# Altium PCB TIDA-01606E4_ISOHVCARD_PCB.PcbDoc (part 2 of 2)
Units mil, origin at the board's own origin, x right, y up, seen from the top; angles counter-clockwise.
Board outline 2900 x 1300 mil, 4 copper layers (Top Layer, Signal Layer 1, Signal Layer 2, Bottom Layer), stack 61.6 mil thick; 82 components, 40 nets, 166 pads, 21 vias.
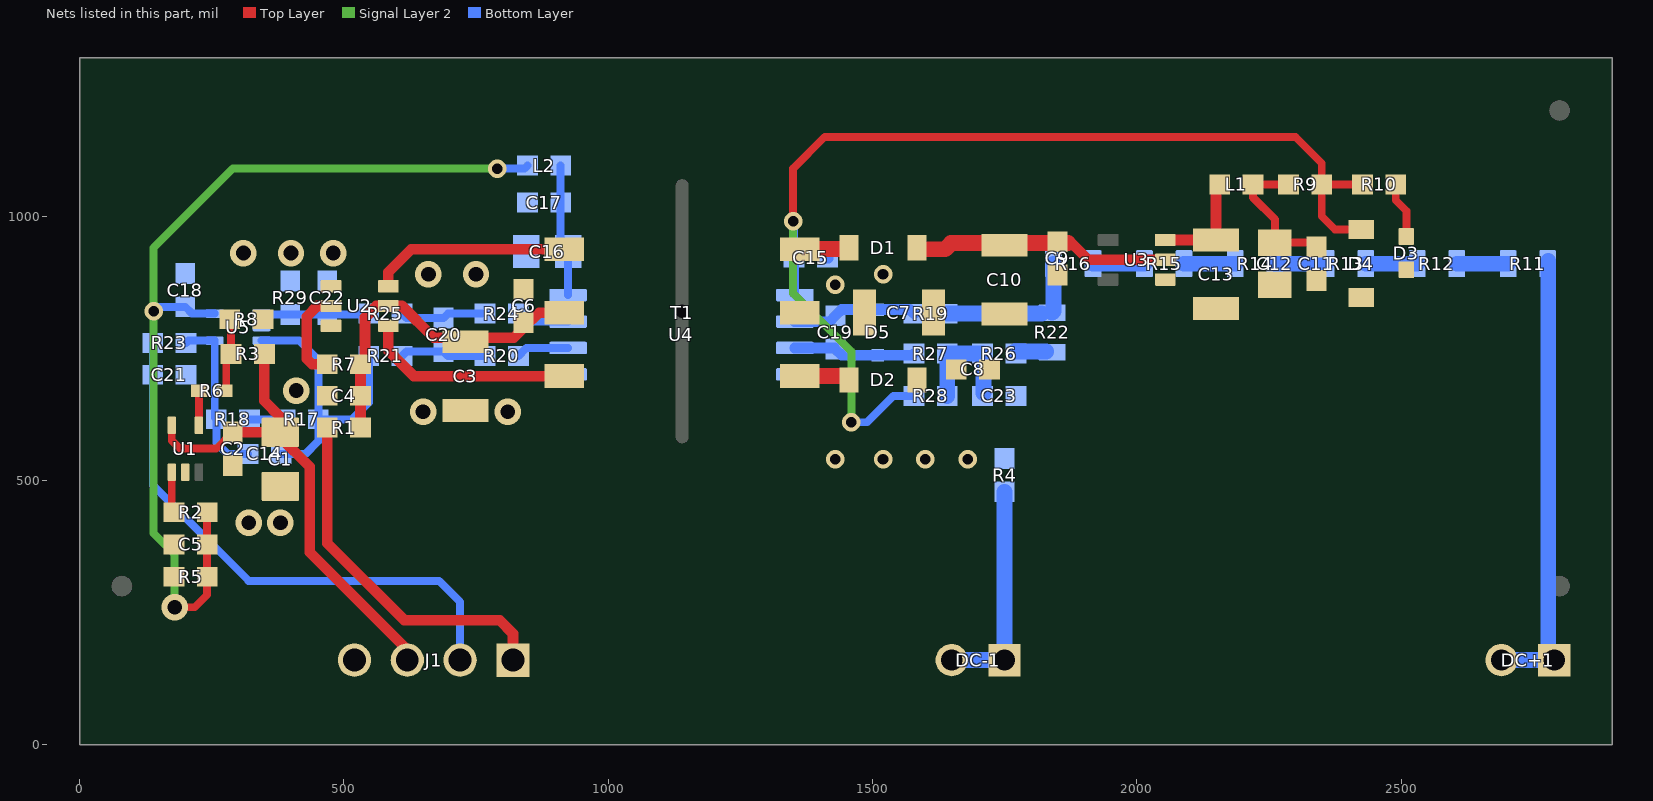
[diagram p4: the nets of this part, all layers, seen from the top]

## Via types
v1: diameter 50, hole 28, Top Layer to Bottom Layer, tented both sides, 11 vias
v2: diameter 35, hole 20, Top Layer to Bottom Layer, tented both sides, 10 vias

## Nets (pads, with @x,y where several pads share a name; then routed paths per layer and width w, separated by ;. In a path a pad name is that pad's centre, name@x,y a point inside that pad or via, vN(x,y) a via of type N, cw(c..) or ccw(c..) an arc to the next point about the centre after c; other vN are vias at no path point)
3.3V: C1.1 C2.2 J1.3 R3.2 U1.5 | length 945.2
  Top Layer w15: U1.5@174.41,604.29 174.41,575.59 190,560 258.5,560 C2.2@290,591.5
  Top Layer w20: C2.2@290,591.5 290.31,591.18 C1.1@380,591.18 ; R3.2@349.61,739.26 349.61,650.39 380,620 C1.1@380,591.18 ; J1.3@620,160 620,180 435.55,364.45 435.55,525.55 380,581.1 C1.1@380,591.18
3.3V_ISO: C15.2 D4.1 R9.2 R10.1 R28.1 U4.1 | length 2108.8
  Top Layer w15: v2(1350,990) 1350,1090 1410,1150 2300,1150 2350,1100 R9.2@2350,1060 ; D4.1@2420,974.47 2375.53,974.47 2350,1000 R9.2@2350,1060 ; R10.1@2427.01,1060 R9.2@2350,1060
  Signal Layer 2 w15: v2(1350,990) 1350,853.82 1460,743.82 v2(1460,610)
  Bottom Layer w15: v2(1350,990) 1351.76,988.24 C15.2@1351.76,921.55 1353.27,920.04 U4.1@1353.27,850.55 ; v2(1460,610) 1489.93,610 1539.93,660 ; 1539.97,659.97 R28.1@1578.52,659.97
3.3V_LS: C5.2 C18.1 L2.2 R2.1 R5.1 U5.5 | length 1830.4
  Top Layer w15: v1(180,260) 217.84,260 241.5,283.65 R5.1@241.5,317.71 R2.1@241.5,450
  Signal Layer 2 w15: v1(180,260) 180,360 140,400 v2(140,820) 140,940 290,1090 v2(790,1090)
  Bottom Layer w15: v2(140,820) 148.5,828.5 C18.1@200,828.5 212.91,815.59 U5.5@255.71,815.59 ; v2(790,1090) 841.65,1090 L2.2@847.2,1095.55
5V: J1.1 R1.2 | length 691
  Top Layer w20: R1.2@468.5,600 468.5,381.5 614.63,235.37 794.63,235.37 820,210 J1.1@820,160
6V: C7.1 C8.1 C9.1 C10.2 D1.1 D2.1 U3.2 | length 487.5
  Top Layer w20: 1870,948.94 1877.01,948.94 1908.5,917.45 U3.2@2054.13,917.45
  Top Layer w30: D1.1@1584.47,937.45 1637.45,937.45 1648.94,948.94 1870,948.94
DC+: DC+1.1 DC+1.2 R11.2 | length 860.2
  Bottom Layer w30: DC+1.2@2690,160 DC+1.1@2790,160 2778.7,171.3 R11.2@2778.7,915.55
DC-: DC-1.1 DC-1.2 R4.1 | length 418.5
  Bottom Layer w30: DC-1.2@1650,160 DC-1.1@1750,160 1749.93,160.07 R4.1@1750,478.5
GND: C1.2 C2.1 C3.1 C4.1 C5.1 C6.1 C16.1 C17.1 C18.2 C21.2 C22.2 J1.4 R5.2 R8.1 R29.1 U1.2 U2.4 U2.6 U4.5 U5.2
  other v1: 320,420 380,420 650,630 810,630 410,670 660,890 750,890 310,930 400,930 480,930
GND_AMC: C7.2 C8.2 C9.2 C10.1 C11.2 C12.1 C13.1 C15.1 C23.1 D3.1 D4.2 R4.2 R22.1 R26.1 T1.5 U3.1 U4.4 | length 60.9
  Bottom Layer w20: C15.1@1414.75,921.55 C15.1@1416.3,920
  Bottom Layer w30: R26.1@1770.02,744.02 R22.1@1828.72,744.02
  other v2: 1430,540 1520,540 1600,540 1680,540 1430,870 1520,890
NetC3_2: C3.2 C4.2 C6.2 R1.1 R7.1 T1.2 U2.2 | length 642.7
  Top Layer w20: R1.1@531.5,600 R7.1@531.5,720 540,728.5 540,808.35 561.65,830 610,830 670,770 821.5,770 840,788.5 840.67,788.5 869.62,817.45 T1.2@917.36,817.45
NetC11_1: C11.1 C12.2 L1.2 R9.1 | length 276.3
  Top Layer w15: R9.1@2287.01,1060 L1.2@2220,1060 2220,1035.3 2261.4,993.9 C12.2@2261.4,950 2331.5,950 C11.1@2340,941.5
NetC13_2: C13.2 L1.1 U3.3 | length 203.9
  Top Layer w20: U3.3@2054.13,954.85 2149.89,954.85 C13.2@2150,954.96 2150,1052.99 L1.1@2157.01,1060
NetC14_1: C14.1 R17.1 R21.2 U5.3 | length 553.5
  Bottom Layer w15: U5.3@344.29,764.41 415.59,764.41 451.69,728.31 R17.1@451.69,615.55 ; C14.1@381.5,550 427.27,550 451.69,574.43 R17.1@451.69,615.55 ; R21.2@547.2,735.55 547.2,647.2 515.55,615.55 R17.1@451.69,615.55
NetC14_2: C14.2 R18.1 R23.1 U5.4 | length 319
  Bottom Layer w15: R23.1@201.5,760 205.91,764.41 U5.4@255.71,764.41 255.71,618.54 R18.1@258.7,615.55 258.7,571.3 280,550 C14.2@318.5,550
NetC16_2: C16.2 C17.2 L2.1 U4.8 | length 251.2
  Bottom Layer w15: L2.1@910.2,1095.55 C17.2@910.2,1025.55 910.2,947.5 C16.2@924.7,933 924.13,932.43 U4.8@924.13,850.55
NetC19_1: C19.1 D5.2 R19.2 U4.2 | length 238.1
  Bottom Layer w20: U4.2@1353.27,800.55 1419.06,800.55 C19.1@1430,811.5 1441.81,823.31 D5.2@1510,823.31 1570.93,823.31 R19.2@1578.72,815.52
NetC19_2: C19.2 D5.1 R27.2 U4.3 | length 232.4
  Bottom Layer w20: U4.3@1353.27,750.55 1427.95,750.55 C19.2@1430,748.5 1441.81,736.69 D5.1@1510,736.69 1575.25,736.69 R27.2@1578.52,739.97
NetC20_1: C20.1 R20.2 R21.1 | length 164.1
  Bottom Layer w15: R21.1@610.2,735.55 618.7,744.06 C20.1@688.7,744.06 697.2,735.55 R20.2@767.2,735.55
NetC20_2: C20.2 R24.2 R25.1 | length 164.1
  Bottom Layer w15: R25.1@610.2,815.55 618.7,807.05 C20.2@688.7,807.05 697.2,815.55 R24.2@767.2,815.55
NetC22_1: C22.1 R25.2 R29.2 U5.1 | length 201.9
  Bottom Layer w15: U5.1@345.94,814.06 R29.2@398.7,814.06 C22.1@468.7,814.06 545.71,814.06 R25.2@547.2,815.55
NetC23_2: C23.2 R26.2 R27.1 R28.2 | length 217
  Bottom Layer w30: R28.2@1641.51,659.97 R27.1@1641.51,739.97 R26.2@1708.52,739.97 ; C23.2@1710.02,665.52 R26.2@1710.02,735.52
NetD1_2: D1.2 T1.6 | length 92.8
  Top Layer w30: T1.6@1362.64,937.53 D1.2@1455.45,937.53
NetD2_2: D2.2 T1.4 | length 92.8
  Top Layer w30: T1.4@1362.64,697.37 D2.2@1455.45,697.37
NetD3_2: D3.2 R10.2 | length 106.8
  Top Layer w15: R10.2@2490,1060 2490,1030 2510,1010 D3.2@2510,961.5
NetR2_2: R2.2 U1.1 | length 67.4
  Top Layer w15: U1.1@174.41,515.71 174.41,454.09 R2.2@178.5,450
NetR3_1: R3.1 R6.2 R8.2 | length 139.8
  Top Layer w15: R6.2@277.56,670 277.56,730.2 R3.1@286.62,739.26 286.62,802.69 R8.2@284.23,805.09
NetR6_1: R6.1 U1.4 | length 67
  Top Layer w15: R6.1@222.44,670 225.59,666.85 U1.4@225.59,604.29
NetR7_2: R7.2 U2.5 | length 176.8
  Top Layer w20: R7.2@468.5,720 440,720 430,730 430,810 450,830 U2.5@475.87,830
NetR11_1: R11.1 R12.2 | length 97.2
  Bottom Layer w30: R12.2@2605.4,910 R11.1@2702.6,910
NetR12_1: R12.1 R13.2 | length 97.2
  Bottom Layer w30: R13.2@2433.4,910 R12.1@2530.6,910
NetR13_1: R13.1 R14.2 | length 97.2
  Bottom Layer w30: R14.2@2261.4,910 R13.1@2358.6,910
NetR14_1: R14.1 R15.2 | length 97.2
  Bottom Layer w30: R15.2@2089.4,910 R14.1@2186.6,910
NetR15_1: R15.1 R16.2 | length 97.2
  Bottom Layer w30: R16.2@1917.4,910 R15.1@2014.6,910
NetR16_1: R16.1 R19.1 R22.2 | length 272.2
  Bottom Layer w30: R19.1@1641.71,815.52 R22.2@1820.21,815.52 ; R22.2@1840,817.4 1842.6,820 R16.1@1842.6,910
NetR17_2: R17.2 R18.2 | length 67
  Bottom Layer w15: R18.2@321.69,615.55 R17.2@388.7,615.55
NetR20_1: R20.1 U4.6 | length 100.2
  Bottom Layer w15: R20.1@830.2,735.55 845.2,750.55 U4.6@924.13,750.55
NetR24_1: R24.1 U4.7 | length 100.2
  Bottom Layer w15: R24.1@830.2,815.55 845.2,800.55 U4.7@924.13,800.55
NetT1_1: T1.1 U2.3 | length 377.9
  Top Layer w20: U2.3@584.13,867.4 584.13,894.13 627.53,937.53 T1.1@917.36,937.53
NetT1_3: T1.3 U2.1 | length 400
  Top Layer w20: U2.1@584.13,792.6 584.13,745.87 632.63,697.37 T1.3@917.36,697.37
Vdc_SEN: C21.1 J1.2 R23.2 | length 1051.7
  Bottom Layer w15: R23.2@138.5,760 138.5,491.5 320,310 680,310 720,270 J1.2@720,160
pads on no net: FID1.1 FID2.1 FID3.1 LBL1.0 U1.3 U3.4 U3.5

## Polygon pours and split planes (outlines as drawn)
6V on Top Layer "TOP_LAYER_6V_P000" (solid, remove dead copper, pour order 0): 1560,990 1680,990 1680,630 1560,630
GND_AMC on Top Layer "TOP_LAYER_GND_AMC_P010" (solid, remove dead copper, pour order 10): 1360,1200 2640,1200 2640,520 1360,520
GND on Top Layer "TOP_LAYER_GND_P002" (solid, remove dead copper, pour order 2): 0,1200 900,1200 900,100 0,100
GND_AMC on Bottom Layer "BOTTOM_LAYER_GND_AMC_P012" (solid, remove dead copper, pour order 12): 1360,960 1770,960 1860.5,869.5 1860.5,520 1360,520
GND on Bottom Layer "BOTTOM_LAYER_GND_P006" (solid, remove dead copper, pour order 6): 0,1200 900,1200 900,100 0,100
GND on Bottom Layer "BOTTOM_LAYER_GND_P004" (solid, remove dead copper, pour order 4): 0,1200 900,1200 900,100 0,100
GND on Signal Layer 1 "SIGNAL_LAYER_1_GND_P008" (solid, remove dead copper, pour order 8): 0,1200 900,1200 900,100 0,100
no net on Top Solder "NONET_L-01_P-001" (solid): 982.52,1160 1297.48,1160 1297.48,480 982.52,480
no net on Bottom Solder "NONET_L-01_P-001" (solid): 982.52,1087.37 1297.48,1087.37 1297.48,407.37 982.52,407.37

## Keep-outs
Keep-Out Layer:
  text ".Layer_Name" at -623,-858.49 h60

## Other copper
Top Layer:
  text ".Layer_Name" at -623,-858.49 h60
Bottom Layer:
  text ".Layer_Name" at -623,-858.49 h60

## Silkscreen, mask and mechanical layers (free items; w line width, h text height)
Top Overlay:
  rectangle: 930,150 1230,250
  text "'.PRJ_Number'.PCB_Rev-" at 90,1170 h108.27
  text ".Layer_Name" at -623,-858.49 h60
Bottom Overlay:
  text ".Layer_Name" at -623,-858.49 h60
Top Paste:
  text ".Layer_Name" at -623,-858.49 h60
Bottom Paste:
  text ".Layer_Name" at -623,-858.49 h60
Top Solder:
  text ".Layer_Name" at -623,-858.49 h60
  text ".Layer_Name" at -623,-858.49 h60
Bottom Solder:
  text ".Layer_Name" at -623,-858.49 h60
Drill Guide:
  text ".Layer_Name" at -623,-858.49 h60
M1 Board Outline:
  the board outline again, w10
  text ".Layer_Name" at -623,-858.49 h60
M2 Board Dimensions:
  rectangle: -1075,-400 -700,-275
  rectangle: -1200,-275 -1075,-150
  lines w7: -1200,-275 -200,-275 ; -1075,-400 -1075,-150 ; -950,-400 -950,-150 ; -700,-400 -700,-150 ; -450,-400 -450,-150 ; -1200,-400 -1200,-150 -200,-150 -200,-400 -1200,-400
  text ".Layer_Name" at -623,-858.49 h60
M3 3D STEP Top:
  text ".Layer_Name" at -623,-858.49 h60
M4 3D STEP Bottom:
  text ".Layer_Name" at -623,-858.49 h60
M5 Assembly Top:
  lines w10: -1492,-930.17 5108,-930.17 ; -1492,-726.83 5110,-726.83 ; -1492,-523.5 -1492,-1133.5 2513,-1133.5 5110,-1133.5 5110,-523.5 -1491.5,-523.5 -1491.5,-1133.5 84,-1133.5 ; 973,-1133.5 973,-523.5 ; 2240,-726.83 2240,-523.5 ; 3080,-726.83 3080,-523.5 ; 3702,-1140 3702,-937.17
  text "COMPONENTS MARKED 'DNP' SHOULD NOT BE POPULATED." at -46.5,-318.5 h60
  text "ASSEMBLY VARIANT:" at -47,-434 h60
  text ".VariantName" at 989,-434 h60
  text "PCB VIEWED FROM TOP SIDE" at -1428.5,-655.67 h60
  text "BOARD #:" at 1048,-655.67 h60
  text ".PRJ_Number" at 1593.5,-655.67 h60
  text "REV:" at 2438,-655.67 h60
  text ".PCB_Rev" at 2729.5,-655.67 h60
  text "SVN REV:" at 3276,-655.67 h60
  text ".VersionControl_RevNumber" at 3782,-655.67 h60
  text "TID #:" at 1048,-859 h60
  text ".TID" at 1593.5,-859 h60
  text "PLOT NAME =" at -1428.5,-1064.34 h60
  text ".plot_File_Name" at -623,-1064.34 h60
  text "GENERATED    :" at 1050,-1064.34 h60
  text ".Print_Date" at 1919.5,-1064.34 h60
  text ".Print_Time" at 2648.5,-1064.34 h60
  text "TEXAS INSTRUMENTS" at 3913,-1064.34 h60
M6 Assembly Bottom:
  lines w10: -1492.5,-727.33 5109.5,-727.33 ; -1490.5,-930.67 5109.5,-930.67 ; -84.5,-1140.5 -84.5,-937.67 ; 537.5,-727.33 537.5,-524 ; 1377.5,-727.33 1377.5,-524 ; 2644.5,-1134 2644.5,-524 ; 3533.5,-1134 5109,-1134 5109,-524 -1492.5,-524 -1492.5,-1134 1104.5,-1134 5109.5,-1134 5109.5,-524
  text "COMPONENTS MARKED 'DNP' SHOULD NOT BE POPULATED." at 4902,-318 h60
  text ".VariantName" at 3858,-434 h60
  text "ASSEMBLY VARIANT:" at 4897,-434 h60
  text ".VersionControl_RevNumber" at -164.5,-656.17 h60
  text "SVN REV:" at 341.5,-656.17 h60
  text ".PCB_Rev" at 888,-656.17 h60
  text "REV:" at 1179.5,-656.17 h60
  text ".PRJ_Number" at 2024,-656.17 h60
  text "BOARD #:" at 2569.5,-656.17 h60
  text "PCB VIEWED FROM BOTTOM SIDE" at 5046,-656.17 h60
  text ".TID" at 2024,-859.5 h60
  text "TID #:" at 2569.5,-859.5 h60
  text "TEXAS INSTRUMENTS" at -295.5,-1064.84 h60
  text ".Print_Time" at 969,-1064.84 h60
  text ".Print_Date" at 1698,-1064.84 h60
  text "GENERATED    :" at 2567.5,-1064.84 h60
  text ".plot_File_Name" at 4240.5,-1064.84 h60
  text "PLOT NAME =" at 5046,-1064.84 h60
M9 Title Sheet:
  drawing of 57 lines, arcs and shapes, not listed
  text "1" at -460.16,8036.5 h70
  text "2" at 2035.5,8036.5 h70
  text "3" at 4524.84,8036.5 h70
  text "4" at 7031.51,8036.5 h70
  text "5" at 9530.5,8036.5 h70
  text "6" at 12035.5,8036.5 h70
  text "A" at -1616.5,6893.5 h70
  text "A" at 13183.5,6893.5 h70
  text "B" at -1616.5,4513.5 h70
  text "B" at 13183.5,4513.5 h70
  text "C" at -1616.5,2138.5 h70
  text "C" at 13183.5,2138.5 h70
  text "PROJECT TITLE:" at 10143.5,277.5 h45
  text ".PRJ_Title" at 10193.5,144.17 h70
  text "DESIGNED FOR:" at 10143.5,-23.5 h45
  text ".PRJ_Customer" at 10193.5,-163.5 h70
  text "D" at -1616.5,-231.5 h70
  text "D" at 13183.5,-231.5 h70
  text "FILE NAME:" at 10143.5,-323.5 h45
  text ".PCB_File_Name_No_Path" at 10193.5,-443.5 h70
  text "Texas Instruments (TI) and/or its licensors do not warrant the accuracy or completeness of this specification" at 5174,-605.34 h45
  text "ENGINEER:" at 10143.5,-613.5 h45
  text "LAYOUT BY:" at 11648.5,-613.5 h45
  text "or any information contained therein. TI and/or its licensors do not warrant that this design will meet" at 5129.01,-718 h45
  text ".PRJ_Engineer" at 10193.5,-768.49 h70
  text ".PCB_Layout" at 11699,-768.49 h70
  text "the specifications, will be suitable for your application or fit for any particular purpose, or will operate in" at 5129.01,-830.67 h45
  text ".Layer_Name" at -623,-858.49 h60
  text "ALTIUM DESIGNER VERSION:" at 11648.5,-923.5 h45
  text "an implementation. TI and/or its licensors do not warrant that the design is production worthy. You should" at 5129.01,-943.33 h45
  text "completely validate and test your design implementation to confirm the system functionality for your application." at 5174,-1056 h45
  text ".print_Scale" at 10193.5,-1056.83 h70
  text ".Application_BuildNumber" at 11699,-1056.83 h70
  text "1" at -460.16,-1263.5 h70
  text "2" at 2035.5,-1263.5 h70
  text "3" at 4524.84,-1263.5 h70
  text "4" at 7031.51,-1263.5 h70
  text "5" at 9530.5,-1263.5 h70
  text "6" at 12035.5,-1263.5 h70
M10 Fab Notes:
  drawing of 189 lines, arcs and shapes, not listed
  text "DESIGN INFORMATION" at 11182.02,6356.17 h60
  text "MIN. TRACK WIDTH:" at 10537.46,6224.05 h60
  text "8" at 11633.7,6224.05 h60
  text "MIL" at 11788.46,6224.05 h60
  text "MIN. CLEARANCE:" at 10537.46,6099.92 h60
  text "0.2" at 11573.7,6099.93 h60
  text "mm" at 11788.46,6099.92 h60
  text "MIN. VIA PAD SIZE:" at 10537.46,5975.8 h60
  text "24" at 11603.71,5975.8 h60
  text "MIL" at 11788.46,5975.8 h60
  text "0.05mm (2MIL)" at 11232.46,5845.9 h60
  text "MINIMUM ANNULAR RING" at 10208.23,5837.67 h60
  text "EXTERNAL" at 11940.46,5837.67 h60
  text "PER" at 10408.23,5727.55 h60
  text "IPC-D-275 CLASS 2 LEVEL C" at 10628.23,5727.54 h60
  text "MIL, HOLES" at 12116.46,5627.07 h60
  text "+/-" at 11724,5618.48 h60
  text "+/-" at 12578,5618.48 h60
  text "REGISTRATION TOLERANCES:" at 10208.23,5617.42 h60
  text "METAL" at 11408,5617.42 h60
  text "5" at 11984.2,5617.42 h60
  text "3" at 12817.2,5617.42 h60
  text "MIL" at 12933.46,5617.42 h60
  text "HOLE SIZE TOLERANCE (UNLESS OTHERWISE SPECIFIED):" at 10208.23,5519.1 h60
  text "+/-" at 12578,5516.23 h60
  text "3" at 12817.2,5515.17 h60
  text "MIL" at 12933.46,5515.17 h60
  text "MATERIAL:" at 10133.46,5377.52 h60
  text "FR-4 High Tg" at 11119.9,5249 h60
  text "X" at 10975.46,5241.01 h60
  text "FR-408" at 10554.46,5236.49 h60
  text "OTHER" at 12042.46,5236.49 h60
  text "62 MIL (1.6mm) +/-10%" at 10874.56,5093.46 h60
  text "X" at 10754.46,5091.01 h60
  text "THICKNESS:" at 10208.23,5085.24 h60
  text "OTHER" at 12159.46,5085.24 h60
  text "TOLERANCE:" at 10208.23,4946.92 h60
  text "X" at 11056.46,4946.92 h60
  text "ANSI IPC-6012 TYPE 3 CLASS 2" at 11234.48,4946.92 h60
  text "OTHER +/-" at 11234.46,4802.73 h60
  text "BOW & TWIST:" at 10208.23,4657.54 h60
  text "X" at 11056.46,4657.54 h60
  text "ANSI IPC-6012 TYPE 3 CLASS 2" at 11234.48,4657.54 h60
  text "OTHER +/-" at 11234.46,4510.85 h60
  text "DRILLING:" at 10133.46,4380.23 h60
  text "NC_DRILL FILES" at 11894.46,4275.04 h60
  text "REFERENCE:" at 10208.23,4271.1 h60
  text "X" at 10865.46,4271.01 h60
  text "AS SHOWN" at 11043.46,4271.1 h60
  text "X" at 11766.46,4271.1 h60
  text "OTHER" at 12192.46,4128.85 h60
  text "PTH COPPER THICKNESS:" at 10207.91,4125.32 h60
  text "X" at 11347.14,4125.32 h60
  text "20-30 um" at 11475.14,4125.32 h60
  text "BOARD FINISH:" at 10133.46,3977.73 h60
  text "SILKSCREEN:" at 10288.68,3867.6 h60
  text "X" at 11246.46,3867.6 h60
  text "TOP" at 11363.46,3867.6 h60
  text "X" at 11756.46,3867.6 h60
  text "BOTTOM" at 11874.46,3867.6 h60
  text "SILKSCREEN COLOR:" at 10288.68,3712.41 h60
  text "X" at 11245.46,3712.41 h60
  text "WHITE" at 11363.46,3712.41 h60
  text "OTHER" at 11874.46,3712.41 h60
  text "X" at 11376.46,3568.96 h60
  text "GREEN" at 11494.46,3568.96 h60
  text "OTHER" at 12112.46,3568.96 h60
  text "SOLDER RESIST COLOR:" at 10288.68,3562.1 h60
  text "X" at 11376.46,3414.71 h60
  text "MATTE" at 11494.46,3414.71 h60
  text "SEMI-GLOSS" at 12112,3414.07 h60
  text "IMMERSION GOLD (ENIG)" at 11194.46,3241.94 h60
  text "ENEPIG" at 12532,3234.72 h60
  text "SURFACE FINISH:" at 10133.46,3233.72 h60
  text "X" at 11016.46,3233.72 h60
  text "IMM. TIN/SILVER OR EQUIV" at 10463,3096.4 h60
  text "OTHER" at 11894.46,3092.47 h60
  text "ARRAY/PANEL:" at 10133.46,2937.09 h60
  text "CUT AND TRIM PER M1 BOARD OUTLINE" at 11194.46,2928.87 h60
  text "N.C. ROUTE" at 11194.46,2792.9 h60
  text "X" at 11882.46,2792.9 h60
  text "V. SCORE" at 12060.46,2792.9 h60
  text "CERTIFICATION:" at 10133.46,2663.77 h60
  text "MATERIALS AND WORKMANSHIP FOR ALL PCBS" at 10858.46,2663.77 h60
  text "TO MEET OR EXCEED THE REQUIREMENTS OF:" at 10858.46,2569.71 h60
  text "X" at 10495.97,2441.08 h60
  text "ANSI IPC-A-600F CLASS ->" at 10623.96,2441.08 h60
  text "X" at 12271.97,2441.08 h60
  text "2" at 12381.96,2441.08 h60
  text "1" at 12066.96,2439.58 h60
  text "3" at 12735.96,2439.58 h60
  text "X" at 11307.97,2293.39 h60
  text "RoHS" at 11435.96,2293.39 h60
  text "OTHER" at 12080.36,2293.39 h60
  text "PER ORDER" at 12477.42,2293.39 h60
  text "ALL BOARDS MUST MEET OR EXCEED UL94-V0 REQUIREMENTS." at 10161,2139.57 h60
  text "PCB MUST BEAR THE UL94V-0 UL REGISTERED MATERIAL ID NUMBER" at 10161,2023.5 h60
  text "ADDITIONAL REQUIREMENTS:" at 10133.46,1854.08 h60
  text "MICROSECTION:" at 10208.23,1746.95 h60
  text "YES" at 11113.96,1746.95 h60
  text "REQUIRED" at 11975.46,1602.62 h60
  text "BARE BOARD ELEC. TEST:" at 10208.23,1599.76 h60
  text "NONE" at 11513.96,1599.76 h60
  text "X" at 11857.46,1599.76 h60
  text "PER ORDER" at 12567.46,1599.76 h60
  text "XX MIL VIAS REQUIRE NON-CONDUCTIVE FILL AND PLANARIZE" at 10376.38,1394.82 h59
  text "XX MIL VIAS REQUIRE CONDUCTIVE FILL AND PLANARIZE" at 10384.38,1290.84 h60
  text "OUTER XX MIL TRACES REQUIRE 50 OHM SINGLE-ENDED IMPEDANCE" at 10383.39,1127.46 h58
  text "LAYER 2 & 3 (INNER LAYERS) XX MIL WIDE, XX MIL SPACE / TRACES REQUIRE 100 OHM DIFFERENTIAL IMPEDANCE" at 10375.39,891.74 h60
  text ".Layer_Name" at -623,-858.49 h60
M11 Gerber Information:
  lines w10: -1492,-930.17 5108,-930.17 ; -1492,-726.83 5110,-726.83 ; -1492,-523.5 -1492,-1133.5 2513,-1133.5 5110,-1133.5 5110,-523.5 -1491.5,-523.5 -1491.5,-1133.5 84,-1133.5 ; 973,-1133.5 973,-523.5 ; 2240,-726.83 2240,-523.5 ; 3080,-726.83 3080,-523.5 ; 3702,-1140 3702,-937.17
  text "ALL ARTWORK VIEWED FROM TOP SIDE" at -1428.5,-655.67 h60
  text "BOARD #:" at 1048,-655.67 h60
  text ".PRJ_Number" at 1593.5,-655.67 h60
  text "REV:" at 2438,-655.67 h60
  text ".PCB_Rev" at 2729.5,-655.67 h60
  text "SVN REV:" at 3276,-655.67 h60
  text ".VersionControl_RevNumber" at 3782,-655.67 h60
  text "LAYER NAME =" at -1428.5,-858.49 h60
  text "TID #:" at 1048,-859 h60
  text ".TID" at 1593.5,-859 h60
  text "PLOT NAME =" at -1428.5,-1064.34 h60
  text ".plot_File_Name" at -623,-1064.34 h60
  text "GENERATED    :" at 1050,-1064.34 h60
  text ".Print_Date" at 1919.5,-1064.34 h60
  text ".Print_Time" at 2648.5,-1064.34 h60
  text "TEXAS INSTRUMENTS" at 3913,-1064.34 h60
M12 Stackup:
  drawing of 295 lines, arcs and shapes, not listed
  text "Layer" at 4850.35,6600 h60
  text "Name" at 5260.26,6600 h60
  text "Material" at 6200,6600 h60
  text "Thickness" at 7059.77,6600 h60
  text "Constant" at 7709.6,6600 h60
  text "Board Layer Stack" at 8279.46,6600 h60
  text "Top Overlay" at 5260.26,6480 h60
  text "Top Solder" at 5260.26,6360 h60
  text "Solder Resist" at 6200,6360 h60
  text "0.40mil" at 7059.77,6360 h60
  text "3.5" at 7709.6,6360 h60
  text "1" at 4850.35,6240 h60
  text "Top Layer" at 5260.26,6240 h60
  text "1.40mil" at 7059.77,6240 h60
  text "Dielectric 1" at 5260.26,6120 h60
  text "FR-4" at 6200,6120 h60
  text "8.00mil" at 7059.77,6120 h60
  text "4.2" at 7709.6,6120 h60
  text "2" at 4850.35,6000 h60
  text "Signal Layer 1" at 5260.26,6000 h60
  text "1.40mil" at 7059.77,6000 h60
  text "Dielectric 2" at 5260.26,5880 h60
  text "FR-4" at 6200,5880 h60
  text "40.00mil" at 7059.77,5880 h60
  text "4.2" at 7709.6,5880 h60
  text "3" at 4850.35,5760 h60
  text "Signal Layer 2" at 5260.26,5760 h60
  text "1.40mil" at 7059.77,5760 h60
  text "Dielectric 3" at 5260.26,5640 h60
  text "FR-4" at 6200,5640 h60
  text "8.00mil" at 7059.77,5640 h60
  text "4.2" at 7709.6,5640 h60
  text "4" at 4850.35,5520 h60
  text "Bottom Layer" at 5260.26,5520 h60
  text "1.40mil" at 7059.77,5520 h60
  text "Bottom Solder" at 5260.26,5400 h60
  text "Solder Resist" at 6200,5400 h60
  text "0.40mil" at 7059.77,5400 h60
  text "3.5" at 7709.6,5400 h60
  text "Bottom Overlay" at 5260.26,5280 h60
  text ".Layer_Name" at -623,-858.49 h60
M13 Component Bodies Top:
  text ".Layer_Name" at -623,-858.49 h60
M14 Component Bodies Bottom:
  text ".Layer_Name" at -623,-858.49 h60
M15 Courtyards Top:
  text ".Layer_Name" at -623,-858.49 h60
M16 Courtyards Bottom:
  text ".Layer_Name" at -623,-858.49 h60
Drill Drawing:
  circle w10: c4863.54,5091.18 r27.56
  lines w10: 4835.98,4567.51 4863.54,4581.29 4891.1,4567.51 4877.32,4595.07 4891.1,4622.63 4863.54,4608.85 4835.98,4622.63 4849.76,4595.07 4835.98,4567.51 ; 4835.98,4691.53 4891.1,4691.53 4891.1,4746.66 4835.98,4746.66 4835.98,4691.53 ; 4835.98,4829.34 4849.76,4829.34 4849.76,4815.56 4877.32,4815.56 4877.32,4829.34 4891.1,4829.34 4891.1,4856.9 4877.32,4856.9 4877.32,4870.68 4849.76,4870.68 4849.76,4856.9 4835.98,4856.9 4835.98,4829.34 ; 4835.98,4953.37 4849.76,4953.37 4863.54,4939.59 4877.32,4953.37 4891.1,4953.37 4877.32,4967.15 4891.1,4980.93 4877.32,4980.93 4863.54,4994.71 4849.76,4980.93 4835.98,4980.93 4849.76,4967.15 4835.98,4953.37
  lines w12: 4786,4530.3 8012.8,4530.3 ; 4786,5150.43 8012.8,5150.43 ; 5123.36,4406.27 5123.36,5274.46 ; 5455.06,4406.27 5455.06,5274.46 ; 6090.91,4406.27 6090.91,5274.46 ; 6349.71,4406.27 6349.71,5274.46 ; 6724.46,4406.27 6724.46,5274.46 ; 7447,4406.27 7447,5274.46 ; 4786,4406.27 8012.8,4406.27 8012.8,5274.46 4786,5274.46 4786,4406.27
  text "Symbol" at 4860.42,5187.64 h72
  text "Quantity" at 5160.57,5187.64 h72
  text "Finished Hole Size" at 5492.26,5187.64 h72
  text "Plated" at 6128.12,5187.64 h72
  text "Hole Type" at 6386.92,5187.64 h72
  text "Drill Layer Pair" at 6761.67,5187.64 h72
  text "Hole Tolerance" at 7484.21,5187.64 h72
  text "10" at 5160.57,5063.61 h60
  text "20.00mil (0.508mm)" at 5492.26,5063.61 h60
  text "PTH" at 6128.12,5063.61 h60
  text "Round" at 6386.92,5063.61 h60
  text "Top Layer - Bottom Layer" at 6761.67,5063.61 h60
  text "11" at 5160.57,4939.59 h60
  text "28.00mil (0.711mm)" at 5492.26,4939.59 h60
  text "PTH" at 6128.12,4939.59 h60
  text "Round" at 6386.92,4939.59 h60
  text "Top Layer - Bottom Layer" at 6761.67,4939.59 h60
  text "4" at 5160.57,4815.56 h60
  text "40.00mil (1.016mm)" at 5492.26,4815.56 h60
  text "PTH" at 6128.12,4815.56 h60
  text "Round" at 6386.92,4815.56 h60
  text "Top Layer - Bottom Layer" at 6761.67,4815.56 h60
  text "4" at 5160.57,4691.53 h60
  text "43.31mil (1.100mm)" at 5492.26,4691.53 h60
  text "PTH" at 6128.12,4691.53 h60
  text "Round" at 6386.92,4691.53 h60
  text "Top Layer - Bottom Layer" at 6761.67,4691.53 h60
  text "1" at 5160.57,4567.51 h60
  text "25.00mil (0.635mm)" at 5492.26,4567.51 h60
  text "NPTH" at 6128.12,4567.51 h60
  text "Slot" at 6386.92,4567.51 h60
  text "Top Layer - Bottom Layer" at 6761.67,4567.51 h60
  text "30 Total" at 5160.57,4443.48 h60
  text "Slot definitions :" at 4860.42,4356.66 h60
  text "Routed Path Length" at 5309.86,4356.66 h60
  text "= Calculated from tool start centre position to tool end centre position." at 5848.21,4356.66 h60
  text "Hole Length" at 5309.86,4307.05 h60
  text "= Routed Path Length + Tool Size = Slot length as defined in the PCB layout" at 5648.91,4307.05 h60
  text ".Layer_Name" at -623,-858.49 h60
Mechanical 17:
  text ".Layer_Name" at -623,-858.49 h60
Mechanical 18:
  text ".Layer_Name" at -623,-858.49 h60
Mechanical 19:
  text ".Layer_Name" at -623,-858.49 h60

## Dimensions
0,0 to 2900,0 on M2 Board Dimensions
0,0 to 0,1300 on M2 Board Dimensions
-1200,-400 to -200,-400 on M2 Board Dimensions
